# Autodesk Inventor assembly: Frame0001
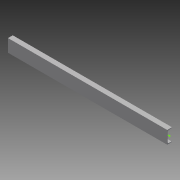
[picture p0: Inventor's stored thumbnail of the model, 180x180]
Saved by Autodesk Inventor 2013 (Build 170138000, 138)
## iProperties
Created: 2009-11
Part Number: Frame0001
Document SubType Name: Assembly
Designer: pokornp
_FrameDoc: Frame Assembly
_Version: 15.0.0
Author: pokornp
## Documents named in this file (3)
- C:\Users\boganb\Documents\B2 Design\Goodyear\2013 Tutorial Files\Frame Analysis 1\side1\Frame\Frame0001.iam
- C:\Users\boganb\Documents\B2 Design\Goodyear\2013 Tutorial Files\Frame Analysis 1\side1\Frame\Skeleton0001.ipt
- C:\Users\boganb\Documents\B2 Design\Goodyear\2013 Tutorial Files\Frame Analysis 1\side1\Frame\DIN U 200 00000001.ipt
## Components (2 placed, 2 different names)
1. Frame Reference Model
2. DIN U 200 00000001:1
